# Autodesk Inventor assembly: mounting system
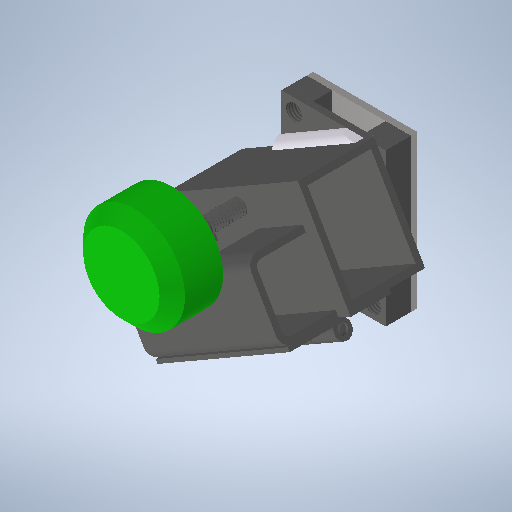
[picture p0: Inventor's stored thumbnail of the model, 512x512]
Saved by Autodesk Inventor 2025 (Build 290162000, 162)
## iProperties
Created: 2024-10
Part Number: mounting system
Document SubType Name: Weldment
Designer: Steven Siewert
Weld Material: Welded Aluminum-6061
Checked By: Usman Attique
Engr Approved By: Darren Fang
Author: Steven Siewert
Title: HOCKEY STICK MOUNT
Comments: BREAK ALL EDGES AND DEBURR ALL HOLES
Revision Number: 1
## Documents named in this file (9)
- C:\Users\steve\Desktop\hockeystik\B\mounting system.iam
- C:\Users\steve\Desktop\hockeystik\B\mounting plate.ipt
- C:\Users\steve\Desktop\hockeystik\B\square bar.ipt
- C:\Users\steve\Desktop\hockeystik\B\swivel.ipt
- C:\Users\steve\Desktop\hockeystik\B\back plate.ipt
- C:\Users\steve\Desktop\hockeystik\B\92965A587_Black-Oxide Grade 5 Steel Hex Head Screws\92965A587_Black-Oxide Grade 5 Steel Hex Head Screws.ipt
- C:\Users\steve\Desktop\hockeystik\B\Part19.ipt
- C:\Users\steve\Desktop\hockeystik\B\16175A61_Steel Hinge without Holes\16175A61_Steel Hinge without Holes.ipt
- C:\Users\steve\Desktop\hockeystik\B\coverplate2.ipt
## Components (10 placed, 8 different names)
1. mounting plate:1 — Rigid:1, Rigid:2, Rotational:1
2. square bar:1 — Rigid:1, Rigid:14
3. square bar:2 — Rigid:2, Rigid:5
4. swivel:1 — Rotational:1, Rigid:11
5. back plate:1 — Rigid:5
6. 92965A587_Black-Oxide Grade 5 Steel Hex Head Screws:1 — Rigid:10, Rigid:13
7. Part19:1 — Rigid:10
8. 16175A61_Steel Hinge without Holes:1 — Rigid:11, Rigid:12
9. coverplate2:1 — Rigid:12, Rigid:13
10. back plate:2 — Rigid:14
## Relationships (9: WeldJoint 8, RevoluteJoint 1)
- Rigid:1 [WeldJoint]: mounting plate:1 ↔ square bar:1
- Rigid:2 [WeldJoint]: mounting plate:1 ↔ square bar:2
- Rotational:1 [RevoluteJoint]: mounting plate:1 ↔ swivel:1
- Rigid:5 [WeldJoint]: square bar:2 ↔ back plate:1
- Rigid:10 [WeldJoint]: 92965A587_Black-Oxide Grade 5 Steel Hex Head Screws:1 ↔ Part19:1
- Rigid:11 [WeldJoint]: swivel:1 ↔ 16175A61_Steel Hinge without Holes:1
- Rigid:12 [WeldJoint]: 16175A61_Steel Hinge without Holes:1 ↔ coverplate2:1
- Rigid:13 [WeldJoint]: 92965A587_Black-Oxide Grade 5 Steel Hex Head Screws:1 ↔ coverplate2:1
- Rigid:14 [WeldJoint]: square bar:1 ↔ back plate:2
## Named parameters: sa_0 = 222411.08076 mm, sa_1 = 0, sa_2 = 0, sa_3 = 1016 mm, sa_4 = 444822.16153 mm, sa_5 = 0, sa_6 = 0, sa_7 = 1016 mm
